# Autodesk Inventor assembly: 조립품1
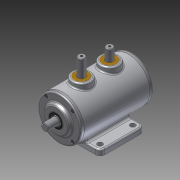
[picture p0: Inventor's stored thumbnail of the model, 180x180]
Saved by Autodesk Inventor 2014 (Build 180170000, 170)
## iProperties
Created: 2014-12
Part Number: 조립품1
Document SubType Name: Assembly
Designer: Owner
Author: Owner
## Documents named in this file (10)
- C:\Users\Owner\Desktop\441223V1008\조립품1.iam
- C:\Users\Owner\Desktop\441223V1008\M4-소켓머리.ipt
- C:\Users\Owner\Desktop\441223V1008\뒷커버.ipt
- C:\Users\Owner\Desktop\441223V1008\베어링 6203.ipt
- C:\Users\Owner\Desktop\441223V1008\본체1.ipt
- C:\Users\Owner\Desktop\441223V1008\부시.ipt
- C:\Users\Owner\Desktop\441223V1008\슬라이더.ipt
- C:\Users\Owner\Desktop\441223V1008\앞커버.ipt
- C:\Users\Owner\Desktop\441223V1008\오일실.ipt
- C:\Users\Owner\Desktop\441223V1008\축1.ipt
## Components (11 placed, 3 different names)
1. 7-베어링 6203:1
2. 8-오일실:1
3. 7-베어링 6203:2
4. 9-M4-소켓머리:1
5. 9-M4-소켓머리:2
6. 9-M4-소켓머리:3
7. 9-M4-소켓머리:4
8. 9-M4-소켓머리:5
9. 9-M4-소켓머리:6
10. 9-M4-소켓머리:7
11. 9-M4-소켓머리:8
